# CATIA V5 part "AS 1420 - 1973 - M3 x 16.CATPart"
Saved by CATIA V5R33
Part number: AS 1420 - 1973 - M3 x 16
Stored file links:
  C:\Users\Ryzen5700u\Desktop\robot_cicloidale_singolo\Assieme_robot_cicloidale_singolo\AS 1420 - 1973 - M3 x 16.CATPart

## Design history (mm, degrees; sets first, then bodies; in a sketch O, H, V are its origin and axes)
Body1 "Solid1" (main body)
  Solid1: solid without history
